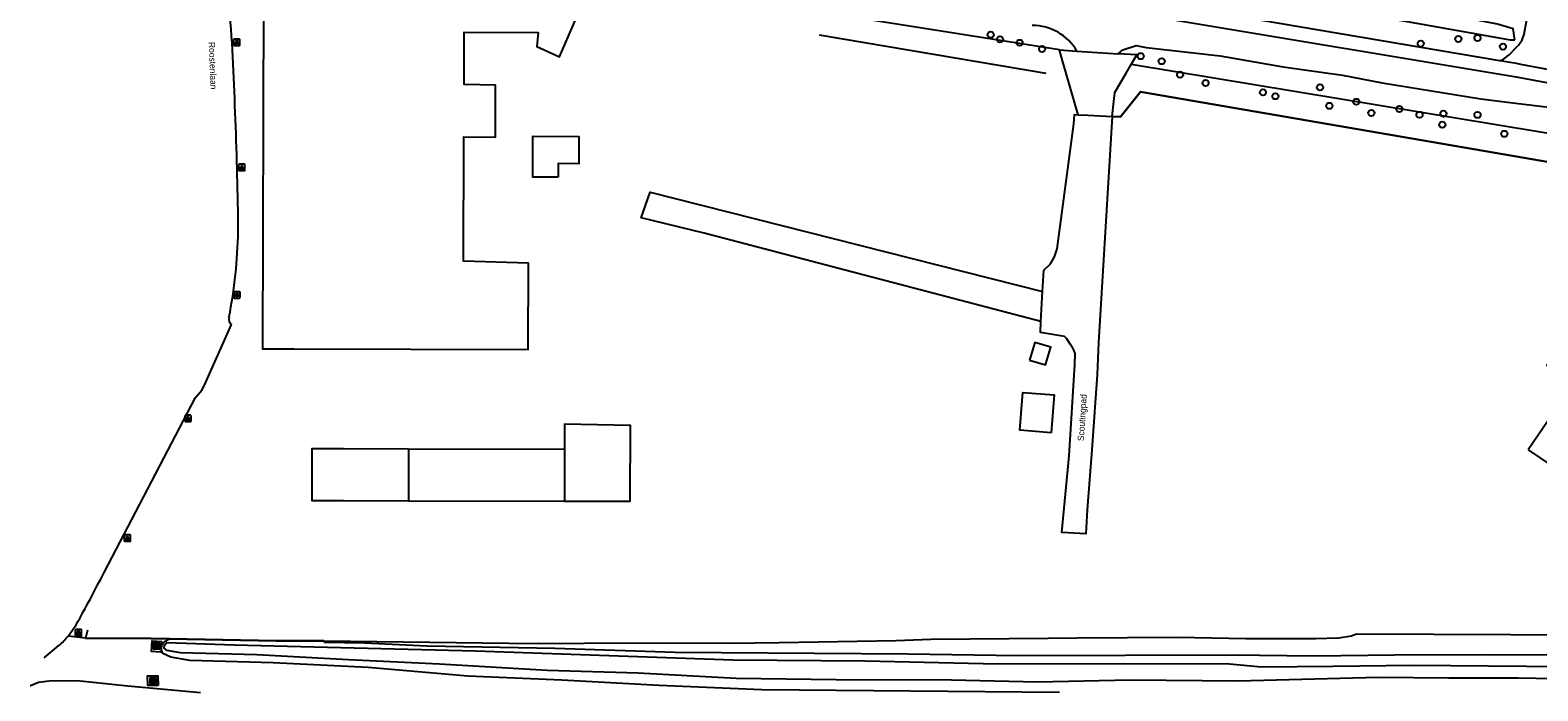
# Model space of a CAD drawing. Extents: x 162157 to 163165, y 378998 to 380775.
# Drawn here: x 162171.3 to 162409.9, y 379597.6 to 379702.1 of the extents above; entities that cross this region are included whole.
import ezdxf

# ---------------------------------------------------------------- set-up
doc = ezdxf.new("R2010")
doc.units = 0
for name, color, linetype in [('IMGEO_Boom', 7, 'Continuous'), ('IMGEO_Fietspad_gesloten', 7, 'Continuous'), ('IMGEO_Groenvoorziening', 7, 'Continuous'), ('IMGEO_Hek', 7, 'Continuous'), ('IMGEO_Lichtpunt', 7, 'Continuous'), ('IMGEO_Loofbos', 7, 'Continuous'), ('IMGEO_Muur', 7, 'Continuous'), ('IMGEO_Open_loods', 7, 'Continuous'), ('IMGEO_Openbare_ruimte_label', 7, 'Continuous'), ('IMGEO_Pand', 7, 'Continuous'), ('IMGEO_Rijbaan_lokaal_gesloten', 7, 'Continuous'), ('IMGEO_Rijbaan_lokaal_onverhard', 7, 'Continuous'), ('IMGEO_Rijbaan_lokaal_open', 7, 'Continuous'), ('IMGEO_Rioolput', 7, 'Continuous'), ('IMGEO_Voetpad_open', 7, 'Continuous'), ('IMGEO_Waterloop', 7, 'Continuous')]:
    doc.layers.add(name, color=color, linetype=linetype)

msp = doc.modelspace()

# ---------------------------------------------------------------- linework, layer by layer
at = {"layer": 'IMGEO_Boom'}
for centre in [(162323.32, 379701.35), (162324.8, 379700.6), (162397.34, 379700.67), (162400.38, 379700.82), (162327.9, 379700.07), (162331.47, 379699.1), (162347.09, 379697.95), (162391.4, 379699.94), (162404.4, 379699.46), (162350.4, 379697.15), (162353.31, 379695.02), (162357.34, 379693.7), (162375.45, 379693.01), (162366.41, 379692.22), (162368.4, 379691.62), (162381.21, 379690.74), (162376.94, 379690.1), (162383.58, 379688.97), (162388.02, 379689.6), (162391.2, 379688.68), (162394.99, 379688.86), (162400.38, 379688.67), (162394.81, 379687.12), (162404.63, 379685.67)]:
    msp.add_circle(centre, 0.489, dxfattribs=at)
at = {"layer": 'IMGEO_Fietspad_gesloten'}
for points in [[(162293.88, 379713.56), (162297.83, 379712.83), (162406.51, 379694.67), (162426.26, 379691.02), (162431.74, 379689.86)], [(162403.9, 379697.22), (162359.69, 379704.68), (162325.62, 379710.33)]]:
    msp.add_lwpolyline(points, dxfattribs=at)
at = {"layer": 'IMGEO_Groenvoorziening'}
for points in [[(162423.76, 379680.09), (162422.68, 379679.3), (162406.25, 379682.13), (162347.07, 379692.29), (162343.87, 379688.35), (162342.56, 379688.42)], [(162193.39, 379605.8), (162190.49, 379605.85), (162180.07, 379605.9), (162177.32, 379606.25)], [(162192.09, 379604.77), (162191.99, 379603.7), (162190.5, 379603.81), (162190.63, 379605.52), (162192.11, 379605.41), (162192.09, 379604.77)], [(162192.09, 379604.77), (162192.6, 379605.42), (162193.39, 379605.8)], [(162217.87, 379605.5), (162210.27, 379605.48), (162193.39, 379605.8)], [(162217.87, 379605.5), (162247.08, 379605.11), (162255.15, 379605.08), (162262.9, 379605.2), (162282.05, 379605.15), (162289.85, 379605.22), (162308.4, 379605.53), (162313.87, 379605.74), (162332.41, 379605.9), (162337.03, 379605.95), (162352.97, 379606.09), (162363.72, 379605.88), (162374.72, 379605.85), (162378.4, 379605.96), (162380.44, 379606.31), (162381.21, 379606.63), (162576.44, 379605.74), (162576.49, 379606.38)], [(162583.87, 379601.63), (162573.91, 379602.07), (162557.68, 379602.05), (162525.01, 379602.55), (162508.94, 379602.64), (162492.71, 379602.92), (162478.54, 379602.81), (162464.08, 379603.1), (162450.91, 379602.84), (162417.45, 379603.23), (162402.03, 379603.27), (162387.27, 379603.21), (162374.55, 379603.06), (162361.54, 379603.25), (162327.73, 379603.13), (162310.18, 379603.37), (162273.39, 379603.64), (162254.33, 379604.29), (162234.09, 379604.68), (162224.23, 379605.14), (162217.88, 379605.23), (162217.87, 379605.5)], [(162334.23, 379597.34), (162287.14, 379597.73), (162270.89, 379598.43), (162255.44, 379599.26), (162240.59, 379599.92), (162224.79, 379601.29), (162209.76, 379602.03), (162196.6, 379602.38), (162193.56, 379602.9), (162192.29, 379603.47), (162192.12, 379604), (162192.09, 379604.77)], [(162171.31, 379598.43), (162171.36, 379598.45), (162172.66, 379598.95), (162174.33, 379599.15), (162178.75, 379599.23), (162186.78, 379598.4), (162198.3, 379597.35)], [(162191.55, 379598.45), (162189.92, 379598.44), (162189.91, 379599.95), (162191.54, 379599.97), (162191.55, 379598.45)]]:
    msp.add_lwpolyline(points, dxfattribs=at)
at = {"layer": 'IMGEO_Hek'}
for points in [[(162332.13, 379695.19), (162296.26, 379701.27)], [(162342.56, 379688.42), (162343.87, 379688.35), (162347.07, 379692.29), (162406.25, 379682.13)], [(162337.17, 379688.68), (162338.71, 379688.6)], [(162338.71, 379688.6), (162341.61, 379688.46)], [(162341.61, 379688.46), (162342.56, 379688.42)], [(162406.25, 379682.13), (162422.68, 379679.3), (162423.76, 379680.09)]]:
    msp.add_lwpolyline(points, dxfattribs=at)
at = {"layer": 'IMGEO_Lichtpunt'}
for p, q in [((162204.43, 379700.64), (162203.62, 379700.64)), ((162204.43, 379700.64), (162203.62, 379700.64)), ((162203.52, 379700.54), (162203.52, 379699.74)), ((162203.52, 379700.54), (162203.52, 379699.74)), ((162203.62, 379699.64), (162204.43, 379699.64)), ((162203.62, 379699.64), (162204.43, 379699.64)), ((162204.52, 379699.74), (162204.52, 379700.54)), ((162204.52, 379699.74), (162204.52, 379700.54)), ((162204.31, 379680.76), (162204.31, 379679.95)), ((162204.31, 379680.76), (162204.31, 379679.95)), ((162205.21, 379680.85), (162204.4, 379680.85)), ((162205.21, 379680.85), (162204.4, 379680.85)), ((162204.4, 379679.86), (162205.21, 379679.86)), ((162204.4, 379679.86), (162205.21, 379679.86)), ((162205.31, 379679.95), (162205.31, 379680.76)), ((162205.31, 379679.95), (162205.31, 379680.76)), ((162203.54, 379660.6), (162203.54, 379659.8)), ((162203.54, 379660.6), (162203.54, 379659.8)), ((162204.44, 379660.7), (162203.63, 379660.7)), ((162204.44, 379660.7), (162203.63, 379660.7)), ((162204.53, 379659.8), (162204.53, 379660.6)), ((162204.53, 379659.8), (162204.53, 379660.6)), ((162203.63, 379659.7), (162204.44, 379659.7)), ((162203.63, 379659.7), (162204.44, 379659.7)), ((162195.8, 379641.06), (162195.8, 379640.26)), ((162195.8, 379641.06), (162195.8, 379640.26)), ((162196.7, 379641.16), (162195.9, 379641.16)), ((162196.7, 379641.16), (162195.9, 379641.16)), ((162196.8, 379640.26), (162196.8, 379641.06)), ((162196.8, 379640.26), (162196.8, 379641.06)), ((162195.9, 379640.16), (162196.7, 379640.16)), ((162195.9, 379640.16), (162196.7, 379640.16)), ((162186.21, 379622.15), (162186.21, 379621.34)), ((162186.21, 379622.15), (162186.21, 379621.34)), ((162187.12, 379622.25), (162186.31, 379622.25)), ((162187.12, 379622.25), (162186.31, 379622.25)), ((162187.21, 379621.34), (162187.21, 379622.15)), ((162187.21, 379621.34), (162187.21, 379622.15)), ((162186.31, 379621.25), (162187.12, 379621.25)), ((162186.31, 379621.25), (162187.12, 379621.25)), ((162178.44, 379607.19), (162178.44, 379606.38)), ((162178.44, 379607.19), (162178.44, 379606.38)), ((162179.35, 379607.29), (162178.54, 379607.29)), ((162179.35, 379607.29), (162178.54, 379607.29)), ((162178.54, 379606.29), (162179.35, 379606.29)), ((162178.54, 379606.29), (162179.35, 379606.29)), ((162179.44, 379606.38), (162179.44, 379607.19)), ((162179.44, 379606.38), (162179.44, 379607.19))]:
    msp.add_line(p, q, dxfattribs=at)
for points in [[(162203.9, 379700.21), (162203.94, 379700.18), (162203.75, 379699.92), (162203.71, 379699.94), (162203.9, 379700.21)], [(162204, 379700.16), (162204.05, 379700.16), (162204.05, 379699.84), (162204, 379699.84), (162204, 379700.16)], [(162204.11, 379700.18), (162204.15, 379700.21), (162204.33, 379699.94), (162204.3, 379699.92), (162204.11, 379700.18)], [(162204.68, 379680.42), (162204.72, 379680.4), (162204.53, 379680.13), (162204.5, 379680.16), (162204.68, 379680.42)], [(162204.78, 379680.38), (162204.83, 379680.38), (162204.83, 379680.05), (162204.78, 379680.05), (162204.78, 379680.38)], [(162204.89, 379680.4), (162204.93, 379680.42), (162205.12, 379680.16), (162205.08, 379680.13), (162204.89, 379680.4)], [(162203.91, 379660.27), (162203.95, 379660.24), (162203.76, 379659.98), (162203.72, 379660), (162203.91, 379660.27)], [(162204.01, 379660.22), (162204.06, 379660.22), (162204.06, 379659.9), (162204.01, 379659.9), (162204.01, 379660.22)], [(162204.12, 379660.24), (162204.16, 379660.27), (162204.35, 379660), (162204.31, 379659.98), (162204.12, 379660.24)], [(162196.18, 379640.73), (162196.21, 379640.7), (162196.03, 379640.44), (162195.99, 379640.47), (162196.18, 379640.73)], [(162196.28, 379640.68), (162196.32, 379640.68), (162196.32, 379640.36), (162196.28, 379640.36), (162196.28, 379640.68)], [(162196.39, 379640.7), (162196.43, 379640.73), (162196.61, 379640.46), (162196.57, 379640.44), (162196.39, 379640.7)], [(162186.59, 379621.81), (162186.63, 379621.79), (162186.44, 379621.52), (162186.4, 379621.55), (162186.59, 379621.81)], [(162186.69, 379621.77), (162186.74, 379621.77), (162186.74, 379621.44), (162186.69, 379621.44), (162186.69, 379621.77)], [(162186.8, 379621.79), (162186.84, 379621.81), (162187.02, 379621.55), (162186.99, 379621.52), (162186.8, 379621.79)], [(162178.82, 379606.85), (162178.86, 379606.83), (162178.67, 379606.56), (162178.63, 379606.59), (162178.82, 379606.85)], [(162178.92, 379606.81), (162178.97, 379606.81), (162178.97, 379606.48), (162178.92, 379606.48), (162178.92, 379606.81)], [(162179.03, 379606.83), (162179.07, 379606.85), (162179.26, 379606.59), (162179.22, 379606.56), (162179.03, 379606.83)]]:
    msp.add_lwpolyline(points, dxfattribs=at)
for centre in [(162204.02, 379700.34), (162204.81, 379680.56), (162204.04, 379660.4), (162196.3, 379640.86), (162186.71, 379621.95), (162178.94, 379606.99)]:
    msp.add_circle(centre, 0.0994, dxfattribs=at)
for centre, start, end in [((162203.62, 379700.54), 90, 180), ((162203.62, 379700.54), 90, 180), ((162204.43, 379700.54), 0, 90), ((162204.43, 379700.54), 0, 90), ((162203.62, 379699.74), 180, 270), ((162203.62, 379699.74), 180, 270), ((162204.43, 379699.74), 270, 0), ((162204.43, 379699.74), 270, 360), ((162204.4, 379680.76), 90, 180), ((162204.4, 379680.76), 90, 180), ((162204.4, 379679.95), 180, 270), ((162204.4, 379679.95), 180, 270), ((162205.21, 379680.76), 0, 90), ((162205.21, 379680.76), 0, 90), ((162205.21, 379679.95), 270, 0), ((162205.21, 379679.95), 270, 360), ((162203.63, 379660.6), 90, 180), ((162203.63, 379660.6), 90, 180), ((162204.44, 379660.6), 0, 90), ((162204.44, 379660.6), 0, 90), ((162203.63, 379659.8), 180, 270), ((162203.63, 379659.8), 180, 270), ((162204.44, 379659.8), 270, 0), ((162204.44, 379659.8), 270, 360), ((162195.9, 379641.06), 90, 180), ((162195.9, 379641.06), 90, 180), ((162196.7, 379641.06), 0, 90), ((162196.7, 379641.06), 0, 90), ((162195.9, 379640.26), 180, 270), ((162195.9, 379640.26), 180, 270), ((162196.7, 379640.26), 270, 0), ((162196.7, 379640.26), 270, 360), ((162186.31, 379622.15), 90, 180), ((162186.31, 379622.15), 90, 180), ((162187.12, 379622.15), 0, 90), ((162187.12, 379622.15), 0, 90), ((162186.31, 379621.34), 180, 270), ((162186.31, 379621.34), 180, 270), ((162187.12, 379621.34), 270, 0), ((162187.12, 379621.34), 270, 360), ((162178.54, 379607.19), 90, 180), ((162178.54, 379607.19), 90, 180), ((162178.54, 379606.38), 180, 270), ((162178.54, 379606.38), 180, 270), ((162179.35, 379607.19), 0, 90), ((162179.35, 379607.19), 0, 90), ((162179.35, 379606.38), 270, 0), ((162179.35, 379606.38), 270, 360)]:
    msp.add_arc(centre, 0.0946, start, end, dxfattribs=at)
at = {"layer": 'IMGEO_Loofbos'}
for points in [[(162334.22, 379698.94), (162276.02, 379708.18), (162252.43, 379723.83), (162232.66, 379729.8), (162201.08, 379730.48)], [(162343.52, 379698.34), (162344.24, 379698.95), (162346.34, 379699.64), (162347.96, 379699.34), (162359.67, 379698.01), (162369.63, 379696.28), (162378.99, 379694.93), (162385.27, 379693.71), (162400.92, 379691.22), (162406.42, 379690.54), (162420.47, 379688.81)], [(162430.28, 379682.33), (162429.51, 379682.78), (162345.56, 379696.61)]]:
    msp.add_lwpolyline(points, dxfattribs=at)
msp.add_arc((162329.97, 379694.68), 8.12, 30.1668, 90.3452, dxfattribs=at)
at = {"layer": 'IMGEO_Muur'}
for points in [[(162180.39, 379607.19), (162180.07, 379605.9)], [(162180.07, 379605.9), (162190.49, 379605.85), (162210.27, 379605.48), (162217.87, 379605.5), (162247.08, 379605.11), (162255.15, 379605.08), (162262.9, 379605.2), (162282.05, 379605.15), (162289.85, 379605.22), (162308.4, 379605.53), (162313.87, 379605.74), (162332.41, 379605.9)], [(162332.41, 379605.9), (162337.03, 379605.95)], [(162337.03, 379605.95), (162352.97, 379606.09), (162363.72, 379605.88), (162374.72, 379605.85), (162378.4, 379605.96), (162380.44, 379606.31), (162381.21, 379606.63)], [(162381.21, 379606.63), (162576.44, 379605.74), (162576.49, 379606.38)]]:
    msp.add_lwpolyline(points, dxfattribs=at)
at = {"layer": 'IMGEO_Open_loods'}
for points in [[(162255.88, 379635.75), (162231.21, 379635.81)], [(162231.19, 379627.66), (162255.86, 379627.59)]]:
    msp.add_lwpolyline(points, dxfattribs=at)
at = {"layer": 'IMGEO_Pand'}
for points in [[(162213.07, 379651.67), (162250.14, 379651.57), (162250.18, 379665.21), (162239.91, 379665.52), (162239.96, 379684.79), (162239.96, 379685.18), (162244.95, 379685.17), (162244.97, 379693.37), (162239.99, 379693.48), (162240, 379697.22), (162240.01, 379701.74), (162251.74, 379701.71), (162251.52, 379699.47), (162255.07, 379697.84), (162259.82, 379708.84)], [(162208.22, 379706.6), (162208.07, 379651.68), (162213.07, 379651.67)], [(162254.88, 379678.83), (162250.86, 379678.84), (162250.88, 379685.28), (162258.15, 379685.27), (162258.14, 379680.95), (162254.89, 379680.96), (162254.88, 379678.83)], [(162408.42, 379635.69), (162419.81, 379628), (162426.95, 379638.44), (162431.1, 379635.6), (162441.34, 379650.7), (162433.15, 379656.25), (162431.71, 379655.98), (162430.06, 379657.09), (162429.79, 379658.54), (162425.79, 379661.28), (162425.48, 379660.81), (162421.29, 379663.64), (162411.33, 379649.02), (162415.52, 379646.14), (162408.42, 379635.69)], [(162329.49, 379649.9), (162332.03, 379649.14), (162332.86, 379651.95), (162330.33, 379652.7), (162329.49, 379649.9)], [(162332.92, 379638.41), (162327.93, 379638.8), (162328.4, 379644.79), (162333.38, 379644.4), (162332.92, 379638.41)], [(162255.86, 379627.59), (162266.29, 379627.56), (162266.32, 379639.54), (162255.89, 379639.75), (162255.88, 379635.75)], [(162231.21, 379635.81), (162220.91, 379635.84), (162215.91, 379635.86), (162215.89, 379627.7), (162220.89, 379627.69), (162231.19, 379627.66)], [(162231.21, 379635.81), (162231.19, 379627.66)], [(162255.88, 379635.75), (162255.86, 379627.59)]]:
    msp.add_lwpolyline(points, dxfattribs=at)
at = {"layer": 'IMGEO_Rijbaan_lokaal_gesloten'}
for points in [[(162183.01, 379616.32), (162197.49, 379644), (162198.5, 379645.14), (162198.9, 379645.91), (162203.16, 379655.54)], [(162177.32, 379606.25), (162178.58, 379608.03)], [(162173.52, 379602.83), (162175.92, 379604.79)]]:
    msp.add_lwpolyline(points, dxfattribs=at)
for centre, radius, start, end in [((161851.59, 379678.49), 352.33, 1.5364, 4.4027), ((161695.6, 379666.41), 508.66, 0.4352, 2.4254), ((162126.57, 379671.65), 77.68, 348.8463, 358.9849), ((162203.65, 379656.31), 0.915, 160.322, 237.814), ((161991.49, 379713.35), 214.7, 330.6237, 333.1309), ((162166.58, 379615.14), 13.94, 312.0389, 320.3631)]:
    msp.add_arc(centre, radius, start, end, dxfattribs=at)
at = {"layer": 'IMGEO_Rijbaan_lokaal_onverhard'}
for points in [[(162403.9, 379697.22), (162404.51, 379697.49), (162405.38, 379698.15), (162406.6, 379699.41), (162406.86, 379699.67), (162407.43, 379700.53), (162407.74, 379701.43), (162408.08, 379703.18), (162408.29, 379704.23), (162408.36, 379710.92), (162407.43, 379718.66), (162402.67, 379750), (162400.56, 379766.6), (162399.53, 379777.44), (162398.59, 379783.51), (162394.07, 379815.93), (162388.91, 379854.45), (162387.25, 379866.95), (162383.98, 379890.99), (162369.54, 380000.04), (162352.33, 380129.87), (162352.7, 380129.91)], [(162413.48, 379695.46), (162407.26, 379696.65), (162406.55, 379696.77), (162403.9, 379697.22)], [(162331.29, 379655.97), (162277.99, 379669.94), (162268.01, 379672.39), (162269.44, 379676.44), (162331.54, 379660.72)]]:
    msp.add_lwpolyline(points, dxfattribs=at)
at = {"layer": 'IMGEO_Rijbaan_lokaal_open'}
for points in [[(162331.54, 379660.72), (162331.72, 379664.12), (162332.81, 379665.1), (162333.45, 379666.21), (162333.87, 379667.51), (162336.51, 379687.23), (162336.59, 379688.71), (162337.17, 379688.68)], [(162342.56, 379688.42), (162340.42, 379652.66), (162340.16, 379647.64), (162339.34, 379635.71), (162338.58, 379626.21), (162338.38, 379622.42), (162334.62, 379622.62), (162335.73, 379634.73), (162336.64, 379649.22), (162336.73, 379650.95), (162336.54, 379651.37), (162336.31, 379651.77), (162335.93, 379652.43), (162335.4, 379653.25), (162335.02, 379653.62), (162331.2, 379654.23), (162331.29, 379655.97)], [(162337.17, 379688.68), (162338.71, 379688.6), (162341.61, 379688.46), (162342.56, 379688.42)], [(162331.29, 379655.97), (162331.54, 379660.72)]]:
    msp.add_lwpolyline(points, dxfattribs=at)
at = {"layer": 'IMGEO_Rioolput'}
for p, q in [((162190.89, 379605.18), (162191.74, 379605.18)), ((162190.81, 379604.26), (162190.81, 379605.11)), ((162191.74, 379604.18), (162190.89, 379604.18)), ((162191.3, 379604.96), (162191.33, 379604.96)), ((162191.32, 379604.4), (162191.3, 379604.4)), ((162191.82, 379605.11), (162191.82, 379604.26)), ((162190.3, 379598.76), (162190.3, 379599.62)), ((162190.37, 379599.69), (162191.23, 379599.69)), ((162191.23, 379598.69), (162190.37, 379598.69)), ((162190.79, 379599.47), (162190.81, 379599.47)), ((162190.81, 379598.91), (162190.79, 379598.91)), ((162191.3, 379599.62), (162191.3, 379598.76))]:
    msp.add_line(p, q, dxfattribs=at)
for points in [[(162190.89, 379605.18), (162191.74, 379605.18)], [(162190.81, 379604.26), (162190.81, 379605.11)], [(162191.74, 379604.18), (162190.89, 379604.18)], [(162191.4, 379604.88), (162191.15, 379604.88), (162191.15, 379604.48)], [(162191.15, 379604.48), (162191.28, 379604.48), (162191.28, 379604.65), (162191.29, 379604.65)], [(162191.33, 379604.8), (162191.28, 379604.8), (162191.28, 379604.72)], [(162191.28, 379604.72), (162191.33, 379604.72)], [(162191.33, 379604.62), (162191.4, 379604.48), (162191.54, 379604.48), (162191.48, 379604.61)], [(162191.82, 379605.11), (162191.82, 379604.26)], [(162190.3, 379598.76), (162190.3, 379599.62)], [(162190.37, 379599.69), (162191.23, 379599.69)], [(162191.23, 379598.69), (162190.37, 379598.69)], [(162190.89, 379599.39), (162190.64, 379599.39), (162190.64, 379598.99)], [(162190.64, 379598.99), (162190.76, 379598.99), (162190.76, 379599.15), (162190.77, 379599.15)], [(162190.82, 379599.31), (162190.76, 379599.31), (162190.76, 379599.23)], [(162190.76, 379599.23), (162190.81, 379599.23)], [(162190.82, 379599.12), (162190.89, 379598.99), (162191.03, 379598.99), (162190.96, 379599.12)], [(162191.3, 379599.62), (162191.3, 379598.76)]]:
    msp.add_lwpolyline(points, dxfattribs=at)
for centre, radius, start, end in [((162190.89, 379605.11), 0.0765, 91.552, 178.448), ((162190.89, 379605.11), 0.0765, 91.552, 178.448), ((162191.74, 379605.11), 0.0765, 1.552, 88.448), ((162191.74, 379605.11), 0.0765, 1.552, 88.448), ((162190.89, 379604.26), 0.0765, 181.552, 268.448), ((162190.89, 379604.26), 0.0765, 181.552, 268.448), ((162191.28, 379604.59), 0.0533, 26.0293, 88.6989), ((162191.33, 379604.71), 0.0964, 77.0061, 93.1865), ((162191.31, 379604.91), 0.19, 274.7715, 282.9687), ((162191.35, 379604.76), 0.0378, 276.6634, 79.6772), ((162191.4, 379604.77), 0.109, 350.3612, 89.416), ((162191.4, 379604.77), 0.112, 277.5842, 350.9817), ((162191.38, 379604.56), 0.108, 29.5134, 73.7905), ((162191.74, 379604.26), 0.0765, 271.552, 358.448), ((162191.74, 379604.26), 0.0765, 271.552, 358.448), ((162190.38, 379599.61), 0.0765, 91.552, 178.448), ((162190.38, 379599.61), 0.0765, 91.552, 178.448), ((162190.38, 379598.76), 0.0765, 181.552, 268.448), ((162190.38, 379598.76), 0.0765, 181.552, 268.448), ((162190.77, 379599.1), 0.0533, 26.0293, 88.6989), ((162190.8, 379599.42), 0.19, 274.7715, 282.9687), ((162190.82, 379599.21), 0.0964, 77.0061, 93.1865), ((162190.84, 379599.27), 0.0378, 276.6634, 79.6772), ((162190.89, 379599.28), 0.109, 350.3612, 89.416), ((162190.89, 379599.28), 0.112, 277.5842, 350.9817), ((162190.87, 379599.06), 0.108, 29.5134, 73.7905), ((162191.22, 379599.61), 0.0765, 1.552, 88.448), ((162191.22, 379599.61), 0.0765, 1.552, 88.448), ((162191.22, 379598.76), 0.0765, 271.552, 358.448), ((162191.22, 379598.76), 0.0765, 271.552, 358.448)]:
    msp.add_arc(centre, radius, start, end, dxfattribs=at)
for centre, major_axis, ratio, start_param, end_param in [((162191.3, 379604.68), (-0.387, 0.002), 0.722429, 4.712389, 7.853982), ((162191.33, 379604.68), (-0.39, 0.002), 0.717154, 1.570796, 4.712389), ((162190.79, 379599.19), (-0.387, 0.002), 0.722429, 4.712389, 7.853982), ((162190.81, 379599.19), (-0.39, 0.002), 0.717154, 1.570796, 4.712389)]:
    msp.add_ellipse(centre, major_axis=major_axis, ratio=ratio, start_param=start_param, end_param=end_param, dxfattribs=at)
at = {"layer": 'IMGEO_Voetpad_open'}
for points in [[(162337.17, 379688.68), (162335.24, 379695.41), (162334.72, 379697.2), (162334.22, 379698.94)], [(162334.22, 379698.94), (162336.99, 379698.76)], [(162336.99, 379698.76), (162343.52, 379698.34)], [(162345.56, 379696.61), (162346.47, 379698.15), (162343.52, 379698.34)], [(162342.56, 379688.42), (162342.98, 379692.21), (162343.93, 379693.83), (162344.76, 379695.24), (162345.56, 379696.61)]]:
    msp.add_lwpolyline(points, dxfattribs=at)
at = {"layer": 'IMGEO_Waterloop'}
for points in [[(162406.31, 379700.53), (162406.01, 379702.29), (162403.55, 379702.99), (162391.32, 379705.36), (162374.86, 379707.58), (162351.11, 379711.78), (162323.46, 379716.26), (162322.78, 379716.16), (162322.66, 379715.46), (162322.88, 379714.44), (162331.15, 379713.22), (162353.76, 379709.21), (162364.19, 379707.61), (162389.26, 379703.45), (162405.55, 379700.53), (162406.31, 379700.53)], [(162429.76, 379599.2), (162406.83, 379599.61), (162395.85, 379599.58), (162384.71, 379599.68), (162362.52, 379599.13), (162345.43, 379599.3), (162330.73, 379598.97), (162317.12, 379599.28), (162298.89, 379599.34), (162283.05, 379599.52), (162267.53, 379600.4), (162253.15, 379600.81), (162236.09, 379601.8), (162221.69, 379602.47), (162207.2, 379603.27), (162195.11, 379603.61), (162192.98, 379603.96), (162192.5, 379604.34), (162192.59, 379604.82), (162192.93, 379605.24), (162203.62, 379604.86), (162222.57, 379604.41), (162241.81, 379603.9), (162282.56, 379602.52), (162303.45, 379602.33), (162322.16, 379601.93), (162361.11, 379601.84), (162366.19, 379601.41), (162377.5, 379601.47), (162390.14, 379601.66), (162450.09, 379601.12)]]:
    msp.add_lwpolyline(points, dxfattribs=at)

# ---------------------------------------------------------------- texts
at = {"layer": 'IMGEO_Openbare_ruimte_label'}
for s, rotation, p in [('Roostenlaan', 272.3502, (162199.57, 379700.18)), ('Scoutingpad', 86.3879, (162338.07, 379637.06))]:
    msp.add_text(s, height=1, rotation=rotation, dxfattribs=at).set_placement(p)

doc.saveas('drawing.dxf')
